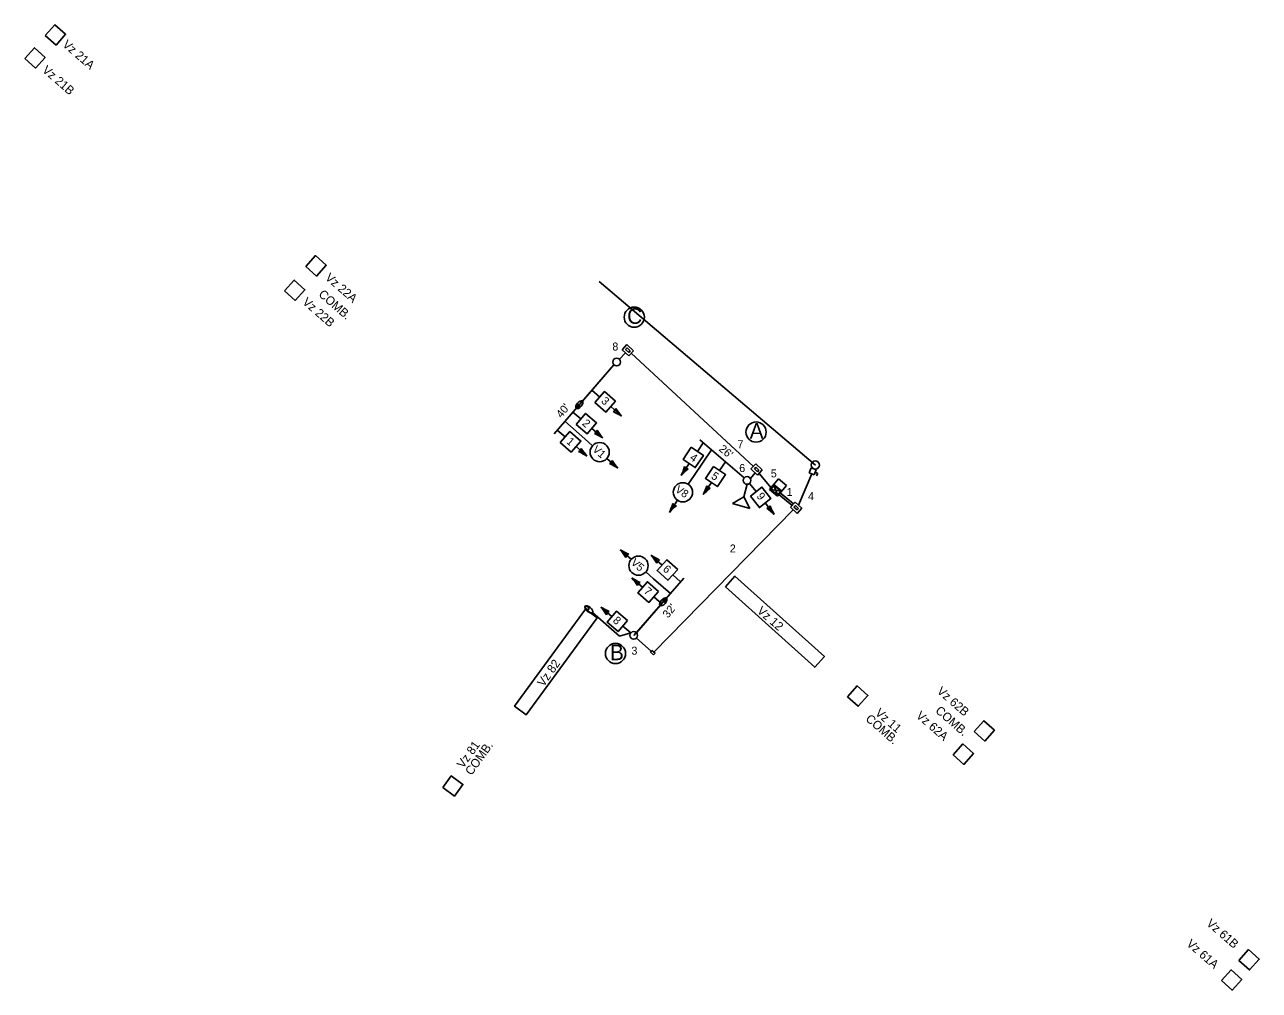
# Model space of a CAD drawing. Extents: x 973817 to 2958182, y 703625 to 1593455.
# Drawn here: x 973817 to 974330, y 707179 to 707580 of the extents above; entities that cross this region are included whole.
import ezdxf

# ---------------------------------------------------------------- set-up
doc = ezdxf.new("R2010")
doc.units = 0
for name, color, linetype in [('S_PAVEMENT_CROWN', 7, 'Continuous'), ('T_Conduit', 7, 'Continuous'), ('T_Detection', 7, 'Continuous'), ('T_Drafting', 7, 'Continuous'), ('T_Indications', 7, 'Continuous')]:
    doc.layers.add(name, color=color, linetype=linetype)

msp = doc.modelspace()

# ---------------------------------------------------------------- linework, layer by layer
at = {"layer": 'S_PAVEMENT_CROWN'}
msp.add_line((974055.77, 707473.62), (974145.76, 707397.3), dxfattribs=at)
at = {"layer": 'T_Conduit'}
for p, q in [((974064.23, 707441.27), (974066.77, 707444)), ((974069.13, 707443.79), (974119.96, 707396.72)), ((974120.71, 707394.03), (974118.73, 707391.7)), ((974122.4, 707393.83), (974127.32, 707387.82)), ((974138.8, 707380.6), (974144.23, 707393.66)), ((974130.6, 707385), (974136.08, 707380.43)), ((974131.18, 707385.7), (974136.7, 707381.1)), ((974078.51, 707319.5), (974136.6, 707378.66)), ((974071.33, 707325.28), (974077.46, 707319.82))]:
    msp.add_line(p, q, dxfattribs=at)
at = {"layer": 'T_Detection'}
for points in [[(973825.36, 707576.01), (973829.82, 707571.99), (973833.83, 707576.46), (973829.37, 707580.47)], [(973816.78, 707566.43), (973821.25, 707562.42), (973825.26, 707566.88), (973820.8, 707570.89)], [(973933.76, 707479.95), (973938.23, 707475.93), (973942.24, 707480.39), (973937.78, 707484.41)], [(973924.91, 707469.76), (973929.37, 707465.75), (973933.38, 707470.21), (973928.92, 707474.22)], [(974108.32, 707346.63), (974112.33, 707351.09), (974149.51, 707317.66), (974145.5, 707313.2)], [(974159.14, 707300.93), (974163.6, 707296.92), (974167.62, 707301.38), (974163.15, 707305.39)], [(974211.82, 707286.49), (974216.28, 707282.48), (974220.29, 707286.94), (974215.83, 707290.95)], [(974203.13, 707276.8), (974207.59, 707272.79), (974211.6, 707277.25), (974207.14, 707281.26)], [(973990.73, 707263.14), (973995.57, 707259.6), (973999.12, 707264.44), (973994.27, 707267.98)], [(974322.01, 707191.26), (974326.47, 707187.25), (974330.48, 707191.71), (974326.02, 707195.72)], [(974314.73, 707182.81), (974319.19, 707178.79), (974323.2, 707183.26), (974318.74, 707187.27)]]:
    msp.add_lwpolyline(points, close=True, dxfattribs=at)
msp.add_lwpolyline([(974050.13, 707337.31), (974054.98, 707333.77), (974025.46, 707293.4), (974020.62, 707296.95), (974050.13, 707337.31)], dxfattribs=at)
at = {"layer": 'T_Drafting'}
for p, q in [((974065.39, 707445.27), (974067.37, 707447.41)), ((974065.39, 707445.27), (974068.14, 707442.72)), ((974066.8, 707445.32), (974067.43, 707446)), ((974066.8, 707445.32), (974068.09, 707444.14)), ((974067.37, 707447.41), (974070.12, 707444.86)), ((974067.43, 707446), (974068.71, 707444.81)), ((974068.09, 707444.14), (974068.71, 707444.81)), ((974068.14, 707442.72), (974070.12, 707444.86)), ((974061.97, 707439.01), (974037.04, 707410.33)), ((974061.97, 707439.01), (974048.85, 707423.91)), ((974116.15, 707391.91), (974097.66, 707407.83)), ((974118.97, 707395.65), (974120.95, 707397.79)), ((974120.95, 707397.79), (974123.7, 707395.24)), ((974118.97, 707395.65), (974121.72, 707393.1)), ((974120.38, 707395.7), (974121.01, 707396.37)), ((974120.38, 707395.7), (974121.67, 707394.51)), ((974121.01, 707396.37), (974122.29, 707395.18)), ((974121.67, 707394.51), (974122.29, 707395.18)), ((974121.72, 707393.1), (974123.7, 707395.24)), ((974143.19, 707394.1), (974144.06, 707396.18)), ((974143.19, 707394.1), (974145.27, 707393.23)), ((974144.06, 707396.18), (974146.14, 707395.31)), ((974145.27, 707393.23), (974146.14, 707395.31)), ((974145.71, 707394.27), (974146.75, 707393.83)), ((974146.31, 707392.79), (974146.75, 707393.83)), ((974117.38, 707389.27), (974115.94, 707384.11)), ((974130.37, 707391.55), (974126.73, 707387.11)), ((974128.51, 707388.76), (974127.2, 707387.15)), ((974130.03, 707384.83), (974127.2, 707387.15)), ((974127.2, 707387.15), (974131.35, 707386.43)), ((974131.82, 707386.48), (974128.47, 707389.23)), ((974131.35, 707386.43), (974128.51, 707388.76)), ((974130.02, 707384.84), (974128.51, 707388.76)), ((974133.72, 707388.8), (974130.08, 707384.36)), ((974133.72, 707388.8), (974130.37, 707391.55)), ((974111.25, 707381.27), (974115.94, 707384.11)), ((974115.94, 707384.11), (974118.48, 707379.25)), ((974130.08, 707384.36), (974126.73, 707387.11)), ((974131.35, 707386.43), (974130.03, 707384.83)), ((974118.48, 707379.25), (974111.25, 707381.27)), ((974135.44, 707379.73), (974137.42, 707381.87)), ((974135.44, 707379.73), (974138.19, 707377.18)), ((974136.85, 707379.78), (974137.47, 707380.46)), ((974136.85, 707379.78), (974138.13, 707378.6)), ((974137.42, 707381.87), (974140.17, 707379.32)), ((974137.47, 707380.46), (974138.76, 707379.27)), ((974138.13, 707378.6), (974138.76, 707379.27)), ((974138.19, 707377.18), (974140.17, 707379.32)), ((974070.19, 707326.41), (974091, 707350.18)), ((974064.31, 707326.11), (974052.99, 707335.95)), ((974071.32, 707327.55), (974081.16, 707338.86)), ((974068.98, 707327.46), (974064.31, 707326.11)), ((974077.16, 707319.49), (974077.78, 707320.17)), ((974077.16, 707319.49), (974078.45, 707318.31)), ((974077.78, 707320.17), (974079.07, 707318.98)), ((974078.45, 707318.31), (974079.07, 707318.98))]:
    msp.add_line(p, q, dxfattribs=at)
for centre, radius in [((974070.42, 707458.81), 4.2), ((974063.1, 707440.14), 1.6), ((974121.09, 707411), 4.2), ((974145.76, 707397.3), 1.69), ((974117.36, 707390.87), 1.6), ((974070.19, 707326.41), 1.6), ((974062.62, 707318.89), 4.2)]:
    msp.add_circle(centre, radius, dxfattribs=at)
for centre, major_axis in [((974047.54, 707422.4), (-1.31, -1.51)), ((974046.88, 707421.65), (0.656, 0.755)), ((974082.47, 707340.37), (1.31, 1.51)), ((974083.13, 707341.13), (-0.656, -0.755)), ((974051.48, 707337.26), (-1.51, 1.31)), ((974050.72, 707337.92), (0.755, -0.656))]:
    msp.add_ellipse(centre, major_axis=major_axis, ratio=0.5, dxfattribs=at)
at = {"layer": 'T_Indications'}
for p, q in [((974052.75, 707428.4), (974056.03, 707425.55)), ((974044.88, 707419.35), (974048.16, 707416.49)), ((974060.62, 707421.58), (974065.17, 707417.61)), ((974041.52, 707415.48), (974049.78, 707408.18)), ((974038.35, 707411.84), (974041.62, 707408.97)), ((974049.78, 707408.18), (974053.02, 707405.31)), ((974049.78, 707408.18), (974049.78, 707408.18)), ((974052.74, 707412.53), (974057.3, 707408.56)), ((974046.19, 707404.99), (974050.73, 707401.01)), ((974102.53, 707403.63), (974095.31, 707392.88)), ((974099.09, 707406.6), (974096.66, 707402.99)), ((974059.01, 707400.01), (974063.56, 707396)), ((974093.29, 707397.95), (974089.92, 707392.94)), ((974108.32, 707398.65), (974105.89, 707395.04)), ((974095.31, 707392.88), (974092.89, 707389.28)), ((974102.52, 707390), (974099.15, 707384.99)), ((974118.41, 707389.66), (974121.11, 707386.25)), ((974088.43, 707382.64), (974085.05, 707377.61)), ((974124.9, 707381.52), (974128.65, 707376.78)), ((974069.16, 707358.08), (974064.6, 707362.08)), ((974081.98, 707355.67), (974077.51, 707359.73)), ((974078.43, 707349.95), (974075.18, 707352.81)), ((974089.69, 707348.67), (974086.48, 707351.6)), ((974073.93, 707346.41), (974069.36, 707350.37)), ((974078.43, 707349.95), (974085.48, 707343.83)), ((974081.82, 707339.62), (974078.53, 707342.46)), ((974061.1, 707334.25), (974056.53, 707338.21)), ((974068.98, 707327.46), (974065.7, 707330.3))]:
    msp.add_line(p, q, dxfattribs=at)
for points in [[(974054.05, 707423.27), (974058.03, 707427.84), (974062.6, 707423.86), (974058.62, 707419.29)], [(974046.18, 707414.22), (974050.16, 707418.79), (974054.73, 707414.81), (974050.75, 707410.23)], [(974039.63, 707406.7), (974043.63, 707411.26), (974048.19, 707407.26), (974044.19, 707402.7)], [(974094.16, 707404.68), (974099.19, 707401.29), (974095.8, 707396.26), (974090.77, 707399.65)], [(974103.39, 707396.73), (974108.42, 707393.34), (974105.03, 707388.31), (974100, 707391.7)], [(974118.75, 707384.38), (974123.5, 707388.15), (974127.27, 707383.4), (974122.51, 707379.63)], [(974088.51, 707353.83), (974084.42, 707349.35), (974079.94, 707353.43), (974084.02, 707357.91)], [(974080.5, 707344.74), (974076.54, 707340.16), (974071.95, 707344.13), (974075.92, 707348.71)], [(974067.67, 707332.58), (974063.7, 707328), (974059.12, 707331.97), (974063.09, 707336.55)]]:
    msp.add_lwpolyline(points, close=True, dxfattribs=at)
for centre in [(974056.02, 707402.66), (974090.66, 707385.96), (974072.17, 707355.44)]:
    msp.add_circle(centre, 4, dxfattribs=at)
for centre, radius, start, end in [((974061.2, 707421.07), 1.63, 287.0785, 350.7731), ((974049.35, 707392.74), 29.47, 57.5341, 65.2723), ((974087.64, 707436.68), 29.47, 212.5794, 220.3175), ((974053.33, 707412.02), 1.63, 287.0785, 350.7731), ((974041.48, 707383.69), 29.47, 57.5341, 65.2723), ((974079.77, 707427.63), 29.47, 212.5794, 220.3175), ((974046.77, 707404.48), 1.63, 286.8816, 350.5763), ((974034.83, 707376.19), 29.47, 57.3372, 65.0754), ((974073.27, 707420), 29.47, 212.3825, 220.1206), ((974059.61, 707399.49), 1.63, 286.6782, 350.3728), ((974047.56, 707371.24), 29.47, 57.1338, 64.8719), ((974086.16, 707414.91), 29.47, 212.1791, 219.9172), ((974063.28, 707405.57), 29.47, 334.6316, 342.3697), ((974111.61, 707373), 29.47, 129.6769, 137.415), ((974092.86, 707397.31), 1.63, 204.176, 267.8706), ((974072.52, 707397.62), 29.47, 334.6316, 342.3697), ((974120.85, 707365.05), 29.47, 129.6769, 137.415), ((974102.09, 707389.36), 1.63, 204.176, 267.8706), ((974058.4, 707390.2), 29.47, 334.7149, 342.453), ((974106.78, 707357.7), 29.47, 129.7602, 137.4983), ((974087.99, 707381.98), 1.63, 204.2593, 267.9539), ((974125.38, 707380.91), 1.63, 276.5755, 340.2701), ((974108.56, 707355.22), 29.47, 47.0311, 54.7692), ((974154.22, 707391.44), 29.47, 202.0764, 209.8145), ((974080.49, 707386.9), 29.47, 237.3786, 245.1167), ((974042.08, 707343.07), 29.47, 32.4238, 40.1619), ((974068.56, 707358.61), 1.63, 106.9229, 170.6176), ((974093.87, 707384.25), 29.47, 236.2845, 244.0226), ((974054.63, 707341.16), 29.47, 31.3298, 39.0679), ((974081.4, 707356.19), 1.63, 105.8289, 169.5235), ((974085.1, 707375.29), 29.47, 237.7294, 245.4675), ((974046.96, 707331.22), 29.47, 32.7747, 40.5128), ((974073.35, 707346.92), 1.63, 107.2738, 170.9684), ((974072.27, 707363.13), 29.47, 237.7294, 245.4675), ((974034.12, 707319.06), 29.47, 32.7747, 40.5128), ((974060.51, 707334.76), 1.63, 107.2738, 170.9684)]:
    msp.add_arc(centre, radius, start, end, dxfattribs=at)

# ---------------------------------------------------------------- texts
at = {"layer": 'S_PAVEMENT_CROWN'}
for s, p in [('8', (974061.3, 707444.92)), ('7', (974113.34, 707404.28)), ('6', (974114.08, 707394.37)), ('5', (974127.22, 707392.16)), ('1', (974133.79, 707384.41)), ('4', (974142.7, 707382.69)), ('2', (974110.16, 707360.92)), ('3', (974069.23, 707318.41))]:
    msp.add_text(s, height=3.33, dxfattribs=at).set_placement(p)
at = {"layer": 'T_Detection'}
for s, rotation, p in [('Vz 21A', 318.9258, (973832.24, 707571.77)), ('Vz 21B', 318.9258, (973823.8, 707561.15)), ('Vz 22A', 318.9258, (973941.53, 707474.78)), ('COMB.', 318.9258, (973938.76, 707467.87)), ('Vz 22B', 318.9258, (973932.08, 707464.63)), ('Vz 12', 318.9258, (974121.22, 707336.16)), ('Vz 82', 54.3691, (974032.67, 707304.79)), ('Vz 62B', 318.9258, (974196.07, 707302.76)), ('Vz 11', 318.9258, (974170.38, 707293.74)), ('Vz 62A', 318.9258, (974187.4, 707292.55)), ('COMB.', 318.9258, (974195.42, 707294.68)), ('COMB.', 318.9258, (974166.37, 707291.26)), ('Vz 81', 54.3691, (973999.24, 707270.86)), ('COMB.', 54.3691, (974002.69, 707267.93)), ('Vz 61B', 318.9258, (974308.2, 707206.16)), ('Vz 61A', 318.9258, (974299.91, 707197.68))]:
    msp.add_text(s, height=3.6, rotation=rotation, dxfattribs=at).set_placement(p)
at = {"layer": 'T_Drafting'}
for s, p in [('C', (974067.45, 707456.03)), ('A', (974118.42, 707408.24)), ('B', (974060.28, 707316.11))]:
    msp.add_text(s, height=6.5, rotation=360, dxfattribs=at).set_placement(p)
at = {"layer": 'T_Indications'}
for s, height, rotation, p in [('3', 3.33, 318.9258, (974056.37, 707423.51)), ("40'", 3.33, 50.3975, (974040.11, 707416.63)), ('2', 3.33, 318.9258, (974048.47, 707414.23)), ('1', 3.33, 318.7289, (974041.94, 707406.66)), ('V1', 3.25, 318.5255, (974052.8, 707403.38)), ("26'", 3.33, 320.3975, (974105.35, 707403.52)), ('4', 3.33, 326.0233, (974093.25, 707399.69)), ('5', 3.33, 326.0233, (974102.11, 707391.99)), ('V8', 3.25, 326.1066, (974087.19, 707386.38)), ('9', 3.33, 308.4228, (974121.11, 707384.28)), ('V5', 3.25, 318.7703, (974068.77, 707356.3)), ('6', 3.33, 317.6762, (974082.03, 707353.63)), ('7', 3.33, 319.1211, (974074.08, 707344.37)), ("32'", 3.33, 50.3975, (974084.43, 707333.38)), ('8', 3.33, 319.1211, (974061.25, 707332.2))]:
    msp.add_text(s, height=height, rotation=rotation, dxfattribs=at).set_placement(p)

doc.saveas('drawing.dxf')
